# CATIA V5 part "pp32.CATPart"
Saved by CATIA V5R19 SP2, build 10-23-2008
Part number: pp32
Publications: "Line.1", "Point.2", "Plane.1", "Point.3", "Line.2", "Plane.2"
Bounding box of the stored display mesh (mm): x -20 to 0, y -270 to 0, z 0 to 50
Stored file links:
  C:\Users\Welcome\Documents\thinkm2\pp32.CATPart
  C:\Users\Welcome\Documents\thinkm2\Brasmeca.CATProduct
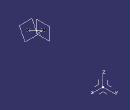
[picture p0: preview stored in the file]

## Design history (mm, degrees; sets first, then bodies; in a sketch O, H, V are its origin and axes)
AxisSystem1: origin (0, 0, 0), X (1, 0, 0), Y (0, 1, 0), Z (0, 0, 1)
Set1
  Point1: linked copy from another document
Body1 (main body)
  Line1: type PtDir, RefPoint Point1, Direction edge [XY plane of AxisSystem1 | ZX plane of AxisSystem1], Start 0, End -20
  Point2: type OnCurve, Support Line1, Length 5
  Plane1: type Normal, Curve Line1, RefPoint Point2
  Point3: (-15, -270, 25), in AxisSystem1
  Line2: type PtPt, FirstPoint Point3, SecondPoint Point2
  Plane2: type Normal, Curve Line2, RefPoint Point3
